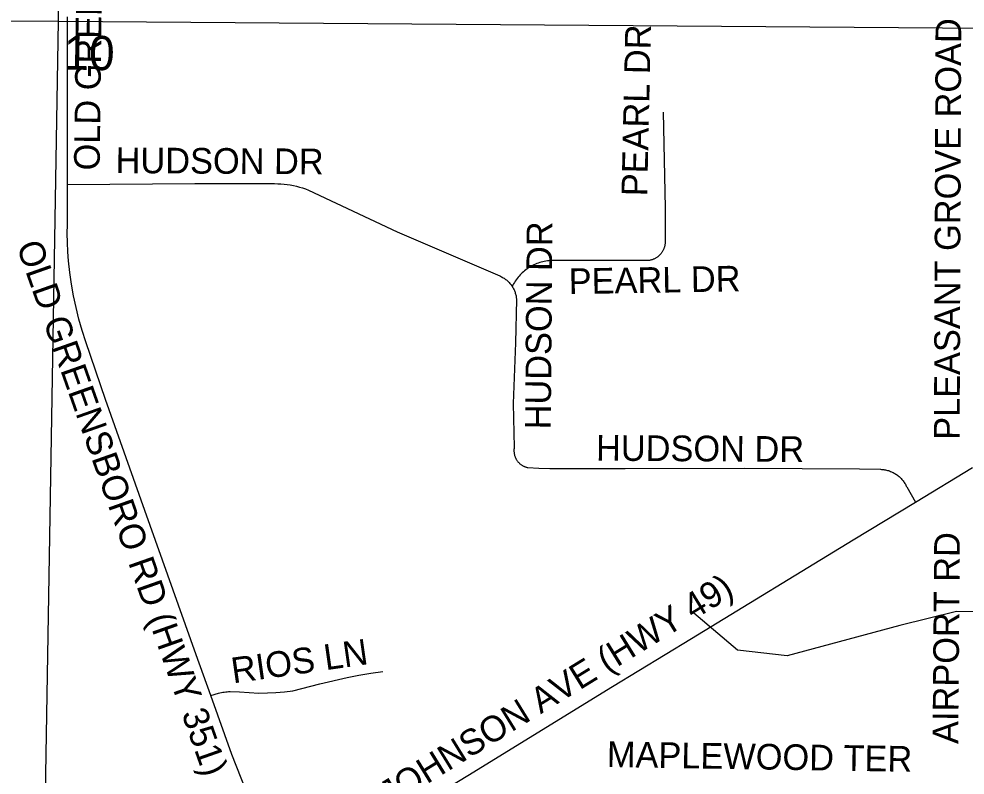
# Model space of a CAD drawing. Extents: x 1670563 to 1761545, y 515755 to 578944.
# Drawn here: x 1709691 to 1712453, y 557782 to 559991 of the extents above; entities that cross this region are included whole.
import ezdxf

# ---------------------------------------------------------------- set-up
doc = ezdxf.new("R2010")
doc.units = 0
for name, color, linetype in [('5_sectionlines', 7, 'Continuous'), ('62_text', 7, 'Continuous'), ('SHP_LINE', 7, 'Continuous'), ('STREETCL', 7, 'Continuous'), ('STRNAMES', 7, 'Continuous')]:
    doc.layers.add(name, color=color, linetype=linetype)

msp = doc.modelspace()

# ---------------------------------------------------------------- linework, layer by layer
at = {"layer": '5_sectionlines'}
for points in [[(1709850.1, 565251.4), (1709805, 559985.3), (1709754.4, 556975)], [(1677977.7, 559756.7), (1683296.8, 559793.9), (1688575.5, 559928.7), (1693867.8, 559919.3), (1699198.2, 559938), (1704504.6, 559990.6), (1709805, 559985.3), (1715121.2, 559943.8), (1715086.8, 558664.7)]]:
    msp.add_lwpolyline(points, dxfattribs=at)
at = {"layer": 'SHP_LINE'}
msp.add_lwpolyline([(1713618, 558255), (1712428, 558260), (1712263, 558219), (1711934, 558131), (1711789, 558147), (1711661, 558255)], dxfattribs=at)
at = {"layer": 'STREETCL'}
for points in [[(1709832.2, 559507.8), (1709832.2, 559662.3), (1709832.2, 559997.4)], [(1711572.2, 559719.1), (1711577.4, 559439.7), (1711577.4, 559343.9), (1711577.5, 559342), (1711577.5, 559340.1), (1711577.5, 559338.2), (1711577.4, 559336.3), (1711577.2, 559334.4), (1711577, 559332.5), (1711576.7, 559330.6), (1711576.3, 559328.7), (1711575.9, 559326.8), (1711575.4, 559325), (1711574.8, 559323.1), (1711574.2, 559321.3), (1711573.5, 559319.5), (1711572.7, 559317.8), (1711571.9, 559316), (1711571, 559314.3), (1711570.1, 559312.6), (1711569.1, 559311), (1711568.1, 559309.4), (1711566.9, 559307.8), (1711565.8, 559306.3), (1711564.6, 559304.8), (1711563.3, 559303.3), (1711562, 559301.9), (1711560.6, 559300.6), (1711559.2, 559299.3), (1711557.8, 559298), (1711556.3, 559296.8), (1711554.7, 559295.7), (1711553.2, 559294.6), (1711551.6, 559293.5), (1711549.9, 559292.6), (1711548.2, 559291.6), (1711546.5, 559290.8), (1711544.8, 559290), (1711543, 559289.2), (1711541.2, 559288.5), (1711539.4, 559287.9), (1711537.6, 559287.3), (1711535.7, 559286.9), (1711533.8, 559286.4), (1711532, 559286.1), (1711530.1, 559285.8), (1711528.2, 559285.5), (1711526.2, 559285.4), (1711408.1, 559285.4), (1711261.1, 559285.4), (1711256.5, 559285.6), (1711252, 559285.8), (1711247.4, 559285.7), (1711242.8, 559285.5), (1711238.3, 559285.1), (1711233.7, 559284.6), (1711229.2, 559283.9), (1711224.7, 559283.1), (1711220.2, 559282.1), (1711215.8, 559281), (1711211.4, 559279.7), (1711207.1, 559278.3), (1711202.8, 559276.7), (1711198.6, 559274.9), (1711194.4, 559273.1), (1711190.3, 559271), (1711186.3, 559268.9), (1711182.3, 559266.6), (1711178.5, 559264.1), (1711174.7, 559261.6), (1711171, 559258.9), (1711167.4, 559256), (1711163.9, 559253.1), (1711160.5, 559250), (1711157.2, 559246.9), (1711154.1, 559243.6), (1711151, 559240.2), (1711148.1, 559236.7), (1711145.3, 559233.1), (1711142.6, 559229.4), (1711140, 559225.6), (1711137.6, 559221.7), (1711135.3, 559217.8), (1711133.1, 559213.7), (1711131.1, 559209.6)], [(1709832.2, 559507.8), (1710204.4, 559510.3), (1710437, 559510.3), (1710446.3, 559510.1), (1710455.5, 559509.7), (1710464.8, 559508.9), (1710474, 559507.8), (1710483.1, 559506.4), (1710492.2, 559504.7), (1710501.2, 559502.7), (1710510.2, 559500.3), (1710519.1, 559497.7), (1710527.9, 559494.8), (1710536.6, 559491.6), (1710795.3, 559369.9), (1711094.5, 559240.8), (1711097.1, 559239.6), (1711099.7, 559238.4), (1711102.2, 559237), (1711104.7, 559235.5), (1711107.1, 559234), (1711109.5, 559232.4), (1711111.8, 559230.7), (1711114, 559228.9), (1711116.2, 559227), (1711118.4, 559225.1), (1711120.4, 559223.1), (1711122.4, 559221), (1711124.3, 559218.9), (1711126.1, 559216.6), (1711127.9, 559214.4), (1711129.5, 559212), (1711131.1, 559209.6)], [(1710250.9, 558015.1), (1710208.5, 558133.6), (1710058.5, 558555.7), (1709943.6, 558879.4), (1709886, 559048.6), (1709875.5, 559081.5), (1709866, 559114.8), (1709857.6, 559148.4), (1709850.4, 559182.2), (1709844.4, 559216.3), (1709839.5, 559250.5), (1709835.7, 559284.9), (1709833.7, 559311.4), (1709832.4, 559337.9), (1709831.9, 559364.4), (1709832.2, 559390.9), (1709832.2, 559507.8)], [(1711131.1, 559209.6), (1711132.5, 559207.3), (1711133.8, 559205), (1711135.1, 559202.6), (1711136.3, 559200.2), (1711137.4, 559197.8), (1711138.4, 559195.3), (1711139.3, 559192.8), (1711140.1, 559190.2), (1711140.9, 559187.6), (1711141.6, 559185), (1711142.2, 559182.4), (1711142.7, 559179.8), (1711143.1, 559177.1), (1711143.4, 559174.5), (1711143.7, 559171.8), (1711140.2, 559045.4), (1711134.3, 558868), (1711136.9, 558739.3), (1711136.6, 558737.7), (1711136.4, 558736), (1711136.2, 558734.3), (1711136.1, 558732.6), (1711136.1, 558730.9), (1711136.1, 558729.2), (1711136.1, 558727.5), (1711136.3, 558725.8), (1711136.4, 558724.1), (1711136.7, 558722.4), (1711137, 558720.7), (1711137.3, 558719.1), (1711137.7, 558717.4), (1711138.2, 558715.8), (1711138.7, 558714.2), (1711139.3, 558712.6), (1711139.9, 558711), (1711140.6, 558709.4), (1711141.3, 558707.9), (1711142.1, 558706.4), (1711142.9, 558704.9), (1711143.8, 558703.4), (1711144.7, 558702)], [(1711144.7, 558702), (1711145.7, 558700.6), (1711146.7, 558699.3), (1711147.8, 558697.9), (1711148.9, 558696.7), (1711150.1, 558695.4), (1711151.3, 558694.2), (1711152.5, 558693), (1711153.8, 558691.9), (1711155.1, 558690.8), (1711156.4, 558689.8), (1711157.8, 558688.8), (1711159.2, 558687.9), (1711160.7, 558687), (1711162.2, 558686.1), (1711163.7, 558685.3), (1711165.2, 558684.6), (1711166.7, 558683.9), (1711168.3, 558683.2), (1711169.9, 558682.6), (1711171.5, 558682.1), (1711173.2, 558681.6), (1711174.8, 558681.2), (1711176.5, 558680.8), (1711208.6, 558678.9), (1711240.8, 558677.9), (1711273, 558677.8), (1711305.2, 558678.5), (1711460.9, 558678.5), (1711810.5, 558679.2), (1712144.8, 558676.9), (1712206.8, 558675.7), (1712209.7, 558675.5), (1712212.7, 558675.3), (1712215.6, 558674.9), (1712218.5, 558674.5), (1712221.4, 558674), (1712224.2, 558673.3), (1712227.1, 558672.6), (1712229.9, 558671.8), (1712232.7, 558670.8), (1712235.4, 558669.8), (1712238.1, 558668.7), (1712240.8, 558667.5), (1712243.5, 558666.2), (1712246, 558664.8), (1712248.6, 558663.3), (1712251.1, 558661.7), (1712253.5, 558660.1), (1712255.9, 558658.4), (1712258.2, 558656.6), (1712260.4, 558654.7), (1712262.6, 558652.7), (1712264.7, 558650.7), (1712266.8, 558648.6), (1712268.8, 558646.4), (1712270.7, 558644.2), (1712272.5, 558641.9), (1712274.2, 558639.5), (1712275.9, 558637.1), (1712277.5, 558634.6), (1712279, 558632.1), (1712280.4, 558629.5), (1712281.7, 558626.9), (1712282.9, 558624.2), (1712308.9, 558580.2)], [(1712308.9, 558580.2), (1712475.3, 558681.4)], [(1710465.6, 557454.8), (1710605.3, 557540.3), (1711001.7, 557781.3), (1711423.9, 558041.2), (1711655, 558181.5), (1712126.3, 558469.4), (1712308.9, 558580.2)], [(1710250.9, 558015.1), (1710273.8, 558021.6), (1710277.9, 558022.7), (1710282, 558023.6), (1710286.2, 558024.4), (1710290.4, 558025.1), (1710294.6, 558025.6), (1710298.8, 558026), (1710303.1, 558026.2), (1710307.3, 558026.2), (1710335.3, 558025.7), (1710363.3, 558024.1), (1710391.2, 558021.6), (1710416.2, 558022.3), (1710441.2, 558023.7), (1710466.1, 558026), (1710490.9, 558029), (1710569.8, 558049), (1710649, 558067.3), (1710683.6, 558074.3), (1710718.4, 558080.2), (1710753.4, 558085)], [(1710465.6, 557454.8), (1710312.7, 557842.8), (1710250.9, 558015.1)]]:
    msp.add_lwpolyline(points, dxfattribs=at)

# ---------------------------------------------------------------- texts
at = {"layer": '62_text'}
msp.add_text('10', height=100, rotation=358.9284, dxfattribs=at).set_placement((1709820.6, 559843.8))
at = {"layer": 'STRNAMES'}
for s, rotation, p in [('OLD GREENSBORO RD (HWY 351)', 89.304, (1709926.5, 559548.5)), ('PLEASANT GROVE ROAD', 89.7803, (1712437.4, 558761.7)), ('PEARL DR', 88.7222, (1711525.1, 559472.8)), ('HUDSON DR', 359.6547, (1709973, 559541)), ('HUDSON DR', 89.5288, (1711243.6, 558792.3)), ('OLD GREENSBORO RD (HWY 351)', 289.4304, (1709683, 559328.9)), ('PEARL DR', 0.9693, (1711296.6, 559187.3)), ('HUDSON DR', 359.6307, (1711375.7, 558701)), ('AIRPORT RD', 89.5288, (1712433.2, 557873.3)), ('JOHNSON AVE (HWY 49)', 31.6258, (1710772.8, 557687.9)), ('RIOS LN', 8.119, (1710316.3, 558050.2)), ('MAPLEWOOD TER', 359.098, (1711407, 557806))]:
    msp.add_text(s, height=75, rotation=rotation, dxfattribs=at).set_placement(p)

doc.saveas('drawing.dxf')
